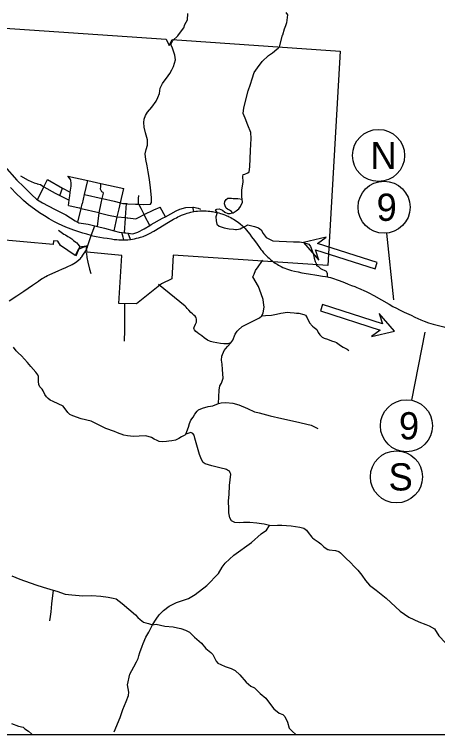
# Model space of a CAD drawing. Extents: x 2025369 to 2161369, y 549489 to 637489.
# Drawn here: x 2047673 to 2058249, y 571561 to 589545 of the extents above; entities that cross this region are included whole.
import ezdxf

# ---------------------------------------------------------------- set-up
doc = ezdxf.new("R2010")
doc.units = 0
for name, color, linetype in [('GM_X_City_Street', 7, 'Continuous'), ('GM_X_Corporation', 7, 'Continuous'), ('GM_X_County_Road', 7, 'Continuous'), ('GM_X_State_Route', 7, 'Continuous'), ('GM_X_Township_Road', 7, 'Continuous'), ('SH_Text', 7, 'Continuous')]:
    doc.layers.add(name, color=color, linetype=linetype)

msp = doc.modelspace()

# ---------------------------------------------------------------- linework, layer by layer
at = {"layer": 'GM_X_City_Street'}
for points in [[(2051077, 584808), (2051096, 584852), (2051099, 584972), (2051074, 585218), (2051049, 585424), (2051019, 585617), (2050990, 585763), (2050956, 585920), (2050941, 586064), (2050967, 586168), (2050998, 586277), (2050996, 586413), (2050950, 586589), (2050919, 586730), (2050906, 586846), (2050914, 586932), (2050946, 587023), (2051000, 587106), (2051106, 587231), (2051218, 587375), (2051260, 587470), (2051298, 587567), (2051319, 587702), (2051375, 587817), (2051516, 588011), (2051557, 588068), (2051609, 588165), (2051645, 588242), (2051701, 588411), (2051681, 588527), (2051638, 588654), (2051612, 588729), (2051579, 588785), (2051596, 588837), (2051634, 588891)], [(2053127, 584590), (2053140, 584591), (2053211, 584637), (2053278, 584691), (2053324, 584752), (2053372, 584853), (2053363, 584932), (2053357, 584991), (2053357, 585157), (2053387, 585362), (2053380, 585494), (2053391, 585546), (2053435, 585555), (2053508, 585587), (2053539, 585613), (2053557, 585742), (2053576, 586149), (2053593, 586447), (2053584, 586597), (2053506, 586776), (2053440, 586952), (2053389, 587073), (2053410, 587214), (2053515, 587637), (2053577, 587806), (2053618, 587937), (2053669, 588093), (2053748, 588211), (2053865, 588373), (2054019, 588523), (2054124, 588585), (2054232, 588674), (2054267, 588699), (2054298, 588732)], [(2046557, 586673), (2046684, 586556), (2046762, 586413), (2046923, 586284), (2047031, 586177), (2047152, 586051), (2047277, 585930), (2047422, 585753), (2047736, 585410), (2047907, 585239), (2048106, 585040), (2048228, 584934), (2048253, 584918), (2048376, 584841), (2048677, 584684), (2048954, 584538), (2049195, 584391), (2049250, 584360), (2049259, 584354)], [(2047823, 585518), (2048016, 585410), (2048163, 585339), (2048231, 585319), (2048243, 585315), (2048283, 585306)], [(2048253, 584918), (2048410, 585239), (2048499, 585421)], [(2048499, 585421), (2048879, 585210), (2049070, 585103)], [(2049011, 585504), (2049511, 585395), (2049832, 585326), (2050404, 585201)], [(2049056, 585007), (2049070, 585103), (2049078, 585157), (2049088, 585252), (2049094, 585332), (2049085, 585396), (2049075, 585422), (2049058, 585445), (2049011, 585504)], [(2049371, 584815), (2049426, 585044), (2049511, 585395)], [(2048283, 585306), (2048324, 585297), (2048410, 585239), (2048692, 585079), (2048812, 585021), (2049042, 584910)], [(2048812, 585021), (2048879, 585210)], [(2049893, 585099), (2049893, 585099), (2049855, 585111), (2049842, 585144), (2049827, 585184), (2049832, 585248), (2049832, 585326)], [(2050289, 584692), (2050289, 584694), (2050323, 584841), (2050404, 585201)], [(2049426, 585044), (2049869, 584949), (2049878, 584947), (2050164, 584879), (2050323, 584841), (2050385, 584826), (2050473, 584821), (2050503, 584819), (2050699, 584809), (2050782, 584804), (2050907, 584796), (2051077, 584808)], [(2049753, 584253), (2049794, 584593), (2049841, 584830), (2049869, 584949), (2049892, 585045), (2049901, 585084), (2049893, 585099)], [(2051058, 584277), (2050935, 584508), (2050917, 584545), (2050839, 584700), (2050782, 584804), (2050775, 584817), (2050776, 584947), (2050784, 585027)], [(2049027, 584777), (2049042, 584910), (2049051, 584976), (2049056, 585007)], [(2053127, 584590), (2053099, 584624), (2053045, 584653), (2053002, 584682), (2052968, 584710), (2052938, 584765), (2052927, 584817), (2052936, 584877), (2052961, 584922), (2053010, 584955), (2053098, 584957), (2053139, 584951), (2053140, 584951)], [(2053140, 584951), (2053174, 584946), (2053254, 584948), (2053363, 584932)], [(2049027, 584777), (2049107, 584756), (2049291, 584713)], [(2049259, 584354), (2049343, 584701), (2049370, 584812), (2049371, 584815)], [(2049291, 584713), (2049298, 584711), (2049343, 584701), (2049785, 584595), (2049793, 584594), (2049794, 584593)], [(2050163, 584137), (2050243, 584492), (2050289, 584692)], [(2050426, 584094), (2050461, 584091), (2050514, 584084), (2050635, 584067), (2050760, 584104), (2050920, 584193), (2051058, 584277), (2051092, 584297), (2051378, 584458), (2051445, 584493), (2051718, 584638), (2051811, 584680), (2051954, 584727), (2052136, 584735), (2052147, 584735), (2052266, 584708), (2052321, 584683)], [(2050450, 584470), (2050473, 584821)], [(2050505, 584465), (2050707, 584443), (2050790, 584483), (2050917, 584545), (2051160, 584663), (2051316, 584729)], [(2051445, 584493), (2051316, 584729)], [(2052159, 584620), (2052136, 584735)], [(2052742, 584599), (2052701, 584662), (2052728, 584684), (2052792, 584686), (2052873, 584659), (2052932, 584611), (2053003, 584570), (2053068, 584572), (2053127, 584590)], [(2049794, 584593), (2050023, 584536), (2050243, 584492), (2050450, 584470), (2050491, 584466), (2050505, 584465)], [(2050426, 584094), (2050449, 584457), (2050450, 584470)], [(2052742, 584599), (2052706, 584494), (2052717, 584392), (2052736, 584308), (2052787, 584259), (2052912, 584216), (2053043, 584187), (2053147, 584179), (2053201, 584176)], [(2049259, 584354), (2049282, 584341), (2049517, 584309), (2049683, 584268), (2049753, 584253), (2049926, 584211), (2050163, 584137), (2050295, 584105), (2050356, 584100), (2050362, 584100), (2050426, 584094)], [(2053201, 584176), (2053221, 584175), (2053277, 584181), (2053316, 584193), (2053357, 584212), (2053403, 584233), (2053428, 584248), (2053506, 584291), (2053673, 584245), (2053774, 584217), (2053841, 584163), (2053893, 584076), (2053965, 583975), (2054129, 583889), (2054291, 583884), (2054471, 583876), (2054649, 583870), (2054795, 583864), (2054895, 583848), (2055032, 583809), (2055071, 583752), (2055139, 583573), (2055168, 583457), (2055187, 583378), (2055219, 583308)], [(2048774, 584158), (2048911, 584059), (2048948, 584044), (2049008, 584001), (2049060, 583975), (2049104, 583942), (2049150, 583901), (2049211, 583861), (2049234, 583840), (2049260, 583810), (2049290, 583767), (2049311, 583738), (2049353, 583746), (2049378, 583751), (2049512, 583776)], [(2049593, 584027), (2049683, 584268)], [(2050408, 583913), (2050391, 583983), (2050356, 584100)], [(2050574, 583924), (2050514, 584084)], [(2049214, 583519), (2049311, 583738)]]:
    msp.add_lwpolyline(points, dxfattribs=at)
at = {"layer": 'GM_X_Corporation'}
msp.add_lwpolyline([(2046697, 589252), (2051467, 588925), (2051538, 588767), (2051612, 588915), (2055813, 588627), (2055503, 583275), (2051637, 583529), (2051605, 582941), (2051349, 582821), (2050728, 582314), (2050282, 582327), (2050354, 583521), (2049488, 583605), (2049465, 583759), (2049263, 583678), (2049195, 583526), (2048827, 583771), (2048760, 583886), (2048654, 583892), (2048645, 583798), (2046411, 583998)], close=True, dxfattribs=at)
at = {"layer": 'GM_X_County_Road'}
for points in [[(2051634, 588891), (2051761, 589011), (2051827, 589105), (2051904, 589208), (2051935, 589295), (2051998, 589412), (2052008, 589566)], [(2052977, 578178), (2052949, 578193), (2052840, 578214), (2052703, 578246), (2052607, 578269), (2052442, 578320), (2052390, 578360), (2052347, 578427), (2052296, 578553), (2052214, 578845), (2052186, 578966), (2052163, 579037), (2052130, 579081), (2052082, 579105), (2051960, 579064), (2051930, 579035), (2051848, 578994), (2051781, 578953), (2051696, 578916), (2051604, 578895), (2051536, 578892), (2051470, 578879), (2051374, 578874), (2051294, 578881), (2051244, 578905), (2051162, 578940), (2051099, 578981), (2050959, 579021), (2050795, 579017), (2050653, 579007), (2050503, 579020), (2050405, 579038), (2050253, 579098), (2050172, 579130), (2049956, 579205), (2049588, 579385), (2049341, 579446), (2049133, 579519), (2049057, 579557), (2049026, 579584), (2049008, 579608), (2048893, 579762), (2048768, 579822), (2048640, 579881), (2048565, 579916), (2048518, 579953), (2048471, 579997), (2048430, 580053), (2048393, 580144), (2048368, 580185), (2048305, 580247), (2048280, 580307), (2048274, 580376), (2048277, 580501), (2048258, 580548), (2048205, 580610), (2048083, 580757), (2048002, 580851), (2047852, 581023), (2047770, 581092), (2047717, 581148), (2047648, 581236)], [(2053845, 576827), (2053731, 576844), (2053554, 576854), (2053402, 576860), (2053306, 576851), (2053178, 576855), (2053099, 576902), (2053056, 576976), (2053035, 577098), (2053034, 577192), (2053024, 577402), (2053036, 577558), (2053045, 577778), (2053083, 578067), (2053069, 578102), (2053045, 578138), (2053000, 578166), (2052977, 578178)], [(2050140, 574967), (2050141, 574967), (2050212, 574950), (2050367, 574834), (2050698, 574549), (2050761, 574484), (2050817, 574437), (2050902, 574372), (2050960, 574349), (2051022, 574335), (2051126, 574305), (2051215, 574446), (2051291, 574553), (2051402, 574664), (2051537, 574768), (2051720, 574864), (2052020, 574956), (2052193, 575062), (2052486, 575288), (2052775, 575580), (2052865, 575741), (2052941, 575842), (2053157, 576043), (2053597, 576360), (2053836, 576573), (2053973, 576669), (2054050, 576782), (2054018, 576790), (2053912, 576816), (2053845, 576827)], [(2047606, 575523), (2047810, 575441), (2048210, 575298), (2048395, 575242), (2048639, 575171), (2048737, 575144), (2048945, 575070), (2049104, 575052), (2049382, 575024), (2049605, 575032), (2049831, 575015), (2050013, 574997), (2050140, 574967)]]:
    msp.add_lwpolyline(points, dxfattribs=at)
at = {"layer": 'GM_X_State_Route'}
for points in [[(2049593, 584027), (2049484, 584055), (2049381, 584083), (2049259, 584120), (2049159, 584155), (2049028, 584206), (2048960, 584234), (2048866, 584274), (2048772, 584319), (2048661, 584377), (2048545, 584440), (2048422, 584513), (2048297, 584593), (2048172, 584681), (2048028, 584792), (2047902, 584898), (2047838, 584957), (2047835, 584962), (2047731, 585057), (2047575, 585220)], [(2049593, 584027), (2049715, 584002), (2049812, 583984), (2049901, 583969), (2049994, 583954), (2050096, 583938), (2050168, 583928), (2050229, 583921), (2050286, 583917), (2050349, 583913), (2050408, 583913), (2050505, 583918), (2050574, 583924), (2050621, 583932), (2050676, 583943), (2050726, 583954), (2050777, 583968), (2050827, 583982), (2050890, 584002), (2050982, 584041), (2051046, 584072), (2051154, 584132), (2051309, 584222), (2051484, 584330), (2051653, 584431), (2051683, 584448), (2051722, 584469), (2051756, 584487), (2051799, 584508), (2051847, 584529), (2051897, 584548), (2051951, 584568), (2051991, 584581), (2052025, 584590), (2052054, 584598), (2052081, 584604), (2052119, 584612), (2052159, 584620), (2052207, 584628), (2052252, 584633), (2052303, 584637), (2052346, 584639), (2052397, 584640), (2052462, 584638), (2052516, 584636), (2052560, 584631), (2052600, 584626), (2052623, 584623), (2052659, 584617), (2052690, 584611)], [(2052690, 584611), (2052707, 584607), (2052742, 584599), (2052779, 584589), (2052821, 584577), (2052856, 584566), (2052910, 584547), (2052950, 584530), (2052981, 584518), (2053012, 584503), (2053041, 584488), (2053079, 584470), (2053114, 584450), (2053149, 584430), (2053190, 584404), (2053227, 584378), (2053261, 584354), (2053313, 584313), (2053370, 584263), (2053403, 584233), (2053439, 584195), (2053472, 584158), (2053510, 584113), (2053553, 584058), (2053602, 583993), (2053672, 583897), (2053738, 583804), (2053795, 583725), (2053834, 583674), (2053861, 583639), (2053900, 583593), (2053941, 583548), (2053964, 583522), (2053989, 583499)], [(2049492, 583720), (2049512, 583776), (2049593, 584027)], [(2048861, 583180), (2048957, 583223), (2049025, 583255), (2049070, 583276), (2049114, 583300), (2049157, 583324), (2049196, 583348), (2049237, 583377), (2049284, 583415), (2049322, 583453), (2049342, 583474), (2049360, 583495), (2049387, 583530), (2049420, 583579), (2049441, 583614), (2049454, 583639), (2049487, 583707), (2049492, 583720)], [(2053989, 583499), (2054007, 583483), (2054037, 583455), (2054075, 583422), (2054115, 583389), (2054156, 583360), (2054193, 583334), (2054238, 583306), (2054274, 583284), (2054337, 583250), (2054382, 583229), (2054430, 583209), (2054476, 583190), (2054527, 583173), (2054600, 583149), (2054676, 583130), (2054761, 583113), (2054856, 583096), (2055024, 583068), (2055235, 583034), (2055371, 583012), (2055451, 582998), (2055494, 582991), (2055519, 582985), (2055574, 582972), (2055622, 582958), (2055675, 582940), (2055716, 582925), (2055789, 582898), (2055921, 582848), (2056015, 582811), (2056096, 582779), (2056177, 582747), (2056230, 582726)], [(2047542, 582389), (2047731, 582516), (2047906, 582635), (2048121, 582782), (2048271, 582885), (2048329, 582925), (2048364, 582948), (2048398, 582970), (2048428, 582986), (2048457, 583002), (2048496, 583022), (2048543, 583042), (2048786, 583147), (2048861, 583180)], [(2056230, 582726), (2056276, 582709), (2056331, 582686), (2056409, 582653), (2056462, 582629), (2056530, 582596), (2056654, 582529), (2056849, 582418), (2057041, 582307), (2057134, 582255), (2057219, 582208), (2057296, 582170), (2057415, 582111), (2057585, 582031), (2057679, 581986), (2057759, 581949), (2057830, 581915), (2057915, 581881), (2058018, 581845), (2058138, 581811), (2058303, 581768), (2058404, 581742), (2058445, 581731), (2058458, 581728)]]:
    msp.add_lwpolyline(points, dxfattribs=at)
at = {"layer": 'GM_X_Township_Road'}
for points in [[(2054458, 589590), (2054499, 589537), (2054482, 589398), (2054475, 589336), (2054450, 589262), (2054417, 589179), (2054374, 589027)], [(2054298, 588732), (2054374, 589027)], [(2049441, 583614), (2049464, 583592), (2049474, 583571), (2049482, 583474), (2049508, 583357), (2049551, 583185), (2049587, 583072)], [(2051960, 579064), (2052022, 579240), (2052051, 579329), (2052080, 579409), (2052137, 579484), (2052178, 579560), (2052239, 579639), (2052274, 579672), (2052372, 579709), (2052513, 579751), (2052633, 579772), (2052771, 579828), (2052782, 579996), (2052790, 580160), (2052809, 580267), (2052852, 580335), (2052889, 580460), (2052877, 580680), (2052869, 580808), (2052852, 580912), (2052855, 581008), (2052919, 581154), (2053000, 581251), (2053078, 581348), (2053130, 581411), (2053188, 581562), (2053241, 581635), (2053263, 581661), (2053368, 581752), (2053511, 581826), (2053801, 581972), (2053859, 582016), (2053890, 582092), (2053912, 582233), (2053897, 582351), (2053890, 582425), (2053836, 582567), (2053774, 582752), (2053632, 582988), (2053661, 583056), (2053702, 583149), (2053765, 583244), (2053859, 583371), (2053885, 583412)], [(2055322, 583201), (2055310, 583217), (2055277, 583245), (2055233, 583270), (2055219, 583308)], [(2055494, 582991), (2055500, 583047), (2055497, 583070), (2055489, 583096), (2055474, 583123), (2055330, 583191), (2055322, 583201)], [(2053078, 581348), (2053029, 581326), (2053004, 581322), (2052955, 581319), (2052910, 581322), (2052821, 581331), (2052728, 581343), (2052638, 581362), (2052576, 581378), (2052499, 581411), (2052413, 581469), (2052357, 581516), (2052280, 581570), (2052237, 581605), (2052208, 581631), (2052171, 581669), (2052163, 581687), (2052159, 581707), (2052163, 581733), (2052173, 581753), (2052199, 581813), (2052220, 581859), (2052225, 581890), (2052226, 581914), (2052225, 581939), (2052216, 581965), (2052208, 581985), (2052193, 582006), (2052159, 582035), (2052127, 582065), (2052085, 582104), (2052032, 582156), (2051992, 582204), (2051962, 582232), (2051940, 582257), (2051270, 582799)], [(2050421, 581383), (2050429, 581664), (2050435, 582100), (2050434, 582323)], [(2053859, 582016), (2053948, 582028), (2054094, 582035), (2054222, 582063), (2054329, 582082), (2054386, 582097), (2054493, 582108), (2054568, 582105), (2054666, 582094), (2054726, 582086), (2054785, 582082), (2054905, 582055), (2054947, 582032), (2054988, 581966), (2055050, 581847), (2055122, 581760), (2055167, 581728), (2055233, 581675), (2055268, 581602), (2055309, 581542), (2055365, 581483), (2055416, 581457), (2055496, 581432), (2055600, 581396), (2055677, 581366), (2055723, 581354), (2055821, 581277), (2055886, 581235), (2055990, 581182), (2056031, 581155)], [(2052771, 579828), (2052838, 579847), (2052958, 579856), (2053132, 579837), (2053284, 579797), (2053501, 579705), (2053676, 579623), (2053685, 579621)], [(2053685, 579621), (2053790, 579593), (2054065, 579520), (2054360, 579454), (2054702, 579381), (2055086, 579289), (2055260, 579207)], [(2054050, 576782), (2054244, 576788), (2054358, 576794), (2054586, 576776), (2054806, 576739), (2054904, 576714), (2054974, 576665), (2055017, 576608), (2055107, 576488), (2055122, 576471), (2055165, 576444), (2055268, 576377), (2055328, 576329), (2055407, 576250), (2055465, 576205), (2055502, 576187), (2055513, 576184), (2055539, 576178), (2055700, 576156), (2055782, 576133), (2055822, 576103), (2055944, 575975), (2056077, 575850), (2056154, 575771), (2056255, 575666), (2056356, 575546), (2056446, 575409), (2056549, 575296), (2056714, 575168), (2056968, 574967), (2057310, 574647), (2057531, 574493), (2057780, 574374), (2057956, 574307), (2057956, 574307)], [(2048639, 575171), (2048602, 574824), (2048581, 574625), (2048566, 574511), (2048550, 574403)], [(2050170, 571629), (2050319, 571991), (2050385, 572184), (2050463, 572389), (2050525, 572538), (2050532, 572624), (2050496, 572802), (2050561, 573069), (2050655, 573254), (2050725, 573381), (2050764, 573462), (2050781, 573528), (2050805, 573610), (2050865, 573769), (2050894, 573835), (2050960, 573996), (2051033, 574121), (2051126, 574305)], [(2051126, 574305), (2051214, 574318), (2051429, 574272), (2051643, 574251), (2051753, 574228), (2051835, 574209), (2051945, 574173), (2052046, 574118), (2052177, 573995), (2052345, 573841), (2052458, 573715), (2052583, 573610), (2052628, 573563), (2052685, 573459), (2052713, 573398), (2052756, 573346), (2052834, 573311), (2052943, 573258), (2053089, 573210), (2053194, 573159), (2053305, 573055), (2053469, 572869), (2053580, 572772), (2053676, 572727), (2053818, 572587), (2053957, 572474), (2054073, 572316), (2054158, 572205), (2054287, 572098), (2054379, 572061), (2054430, 572016), (2054499, 571875), (2054543, 571719), (2054614, 571650), (2054706, 571561)], [(2057956, 574307), (2058039, 574275), (2058170, 574199), (2058276, 574026), (2058444, 573856), (2058647, 573773), (2059036, 573621), (2059239, 573520), (2059474, 573381), (2059688, 573235), (2059944, 573004), (2060203, 572791), (2060461, 572592), (2060714, 572409), (2061057, 572171), (2061217, 572109), (2061330, 572155)], [(2047599, 571842), (2047776, 571776), (2047888, 571743), (2047936, 571706), (2048025, 571649), (2048098, 571584), (2048127, 571561)]]:
    msp.add_lwpolyline(points, dxfattribs=at)
at = {"layer": 'SH_Text'}
for p, q in [((2057159, 582415), (2056981, 584084)), ((2057927, 581607), (2057595, 579911))]:
    msp.add_line(p, q, dxfattribs=at)
msp.add_lwpolyline([(2037369, 631489), (2037369, 571561), (2092420, 571561), (2092420, 631489)], dxfattribs=at)
for points in [[(2056693, 583189), (2056743, 583348), (2055246, 583823), (2055462, 583982), (2054895, 583848), (2055281, 583410), (2055196, 583665)], [(2055376, 582305), (2055325, 582147), (2056818, 581662), (2056601, 581504), (2057169, 581635), (2056786, 582075), (2056870, 581820)]]:
    msp.add_lwpolyline(points, close=True, dxfattribs=at)
for centre in [(2056773, 586023), (2056911, 584730), (2057471, 579273), (2057221, 577997)]:
    msp.add_circle(centre, 650, dxfattribs=at)

# ---------------------------------------------------------------- texts
for s, p in [('N', (2056572, 585683)), ('9', (2056724, 584390)), ('9', (2057283, 578933)), ('S', (2057023, 577657))]:
    msp.add_text(s, height=680, dxfattribs=at).set_placement(p)

doc.saveas('drawing.dxf')
